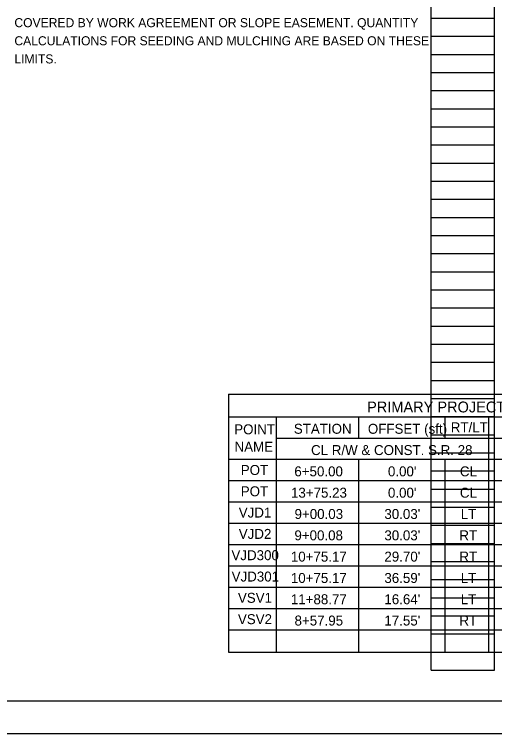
# Model space of a CAD drawing. Extents: x 0 to 34, y 0 to 22.
# Drawn here: x 17.24 to 24.66, y 0 to 11.12 of the extents above; entities that cross this region are included whole.
import ezdxf

# ---------------------------------------------------------------- set-up
doc = ezdxf.new("R2010")
doc.units = 0
for name, color, linetype in [('SH_Border', 7, 'Continuous'), ('SH_Cut_Line', 7, 'Continuous'), ('SH_Data', 7, 'Continuous'), ('SH_Text', 7, 'Continuous')]:
    doc.layers.add(name, color=color, linetype=linetype)

msp = doc.modelspace()

# ---------------------------------------------------------------- linework, layer by layer
at = {"layer": 'SH_Border'}
msp.add_lwpolyline([(1.5, 21.5), (33.5, 21.5), (33.5, 0.5), (1.5, 0.5)], close=True, dxfattribs=at)
at = {"layer": 'SH_Cut_Line'}
msp.add_lwpolyline([(0, 0), (34, 0), (34, 22), (0, 22)], close=True, dxfattribs=at)
at = {"layer": 'SH_Data'}
for p, q in [((23.68, 0.98), (23.68, 21.14)), ((24.66, 0.98), (24.66, 21.14)), ((23.68, 11.06), (24.66, 11.06)), ((23.68, 10.78), (24.66, 10.78)), ((23.68, 10.5), (24.66, 10.5)), ((23.68, 10.22), (24.66, 10.22)), ((23.68, 9.94), (24.66, 9.94)), ((23.68, 9.66), (24.66, 9.66)), ((23.68, 9.38), (24.66, 9.38)), ((23.68, 9.1), (24.66, 9.1)), ((23.68, 8.82), (24.66, 8.82)), ((23.68, 8.54), (24.66, 8.54)), ((23.68, 8.26), (24.66, 8.26)), ((23.68, 7.98), (24.66, 7.98)), ((23.68, 7.7), (24.66, 7.7)), ((23.68, 7.42), (24.66, 7.42)), ((23.68, 7.14), (24.66, 7.14)), ((23.68, 6.86), (24.66, 6.86)), ((23.68, 6.58), (24.66, 6.58)), ((23.68, 6.3), (24.66, 6.3)), ((23.68, 6.02), (24.66, 6.02)), ((23.68, 5.74), (24.66, 5.74)), ((23.68, 5.46), (24.66, 5.46)), ((20.546, 5.245), (30.939, 5.245)), ((20.546, 5.245), (20.546, 1.259)), ((23.68, 5.18), (24.66, 5.18)), ((20.546, 4.899), (30.939, 4.899)), ((21.287, 4.899), (21.287, 1.259)), ((22.555, 4.899), (22.555, 4.569)), ((23.68, 4.9), (24.66, 4.9)), ((23.889, 4.899), (23.889, 4.569)), ((24.564, 4.899), (24.564, 1.259)), ((21.287, 4.569), (27.266, 4.569)), ((23.68, 4.62), (24.66, 4.62)), ((23.68, 4.34), (24.66, 4.34)), ((20.546, 4.24), (30.939, 4.24)), ((22.555, 4.24), (22.555, 1.259)), ((23.889, 4.24), (23.889, 1.259)), ((23.68, 4.06), (24.66, 4.06)), ((20.546, 3.911), (30.939, 3.911)), ((23.68, 3.78), (24.66, 3.78)), ((20.546, 3.581), (30.939, 3.581)), ((23.68, 3.5), (24.66, 3.5)), ((20.546, 3.252), (30.939, 3.252)), ((23.68, 3.22), (24.66, 3.22)), ((20.546, 2.922), (30.939, 2.922)), ((23.68, 2.94), (24.66, 2.94)), ((20.546, 2.593), (30.939, 2.593)), ((23.68, 2.66), (24.66, 2.66)), ((23.68, 2.38), (24.66, 2.38)), ((20.546, 2.264), (30.939, 2.264)), ((23.68, 2.1), (24.66, 2.1)), ((20.546, 1.934), (30.939, 1.934)), ((23.68, 1.82), (24.66, 1.82)), ((20.546, 1.605), (30.939, 1.605)), ((23.68, 1.54), (24.66, 1.54)), ((20.546, 1.259), (30.939, 1.259)), ((23.68, 1.26), (24.66, 1.26)), ((23.68, 0.98), (24.66, 0.98))]:
    msp.add_line(p, q, dxfattribs=at)

# ---------------------------------------------------------------- texts
at = {"layer": 'SH_Text'}
for s, height, p in [('COVERED BY WORK AGREEMENT OR SLOPE EASEMENT. QUANTITY ', 0.14, (17.24, 10.92)), ('CALCULATIONS FOR SEEDING AND MULCHING ARE BASED ON THESE ', 0.14, (17.24, 10.64)), ('LIMITS.', 0.14, (17.24, 10.36)), ('PRIMARY PROJECT CONTROL AND CENTERLINE INFORMATION', 0.168, (22.69, 4.965)), ('POINT', 0.154, (20.637, 4.627)), ('STATION', 0.154, (21.558, 4.635)), ('OFFSET (sft)', 0.154, (22.702, 4.635)), ('RT/LT', 0.154, (23.983, 4.657)), ('NAME', 0.154, (20.642, 4.358)), ('CL R/W & CONST. S.R. 28', 0.154, (21.824, 4.306)), ('POT', 0.154, (20.738, 3.998)), ('6+50.00', 0.154, (21.566, 3.977)), ("0.00'", 0.154, (23.012, 3.977)), ('CL', 0.154, (24.124, 3.977)), ('POT', 0.154, (20.738, 3.669)), ('13+75.23', 0.154, (21.514, 3.647)), ("0.00'", 0.154, (23.012, 3.647)), ('CL', 0.154, (24.124, 3.647)), ('VJD1', 0.154, (20.707, 3.34)), ('9+00.03', 0.154, (21.569, 3.318)), ("30.03'", 0.154, (22.957, 3.318)), ('LT', 0.154, (24.137, 3.318)), ('VJD2', 0.154, (20.707, 3.01)), ('9+00.08', 0.154, (21.567, 2.988)), ("30.03'", 0.154, (22.957, 2.988)), ('RT', 0.154, (24.116, 2.988)), ('VJD300', 0.154, (20.594, 2.681)), ('10+75.17', 0.154, (21.512, 2.659)), ("29.70'", 0.154, (22.957, 2.659)), ('RT', 0.154, (24.116, 2.659)), ('VJD301', 0.154, (20.597, 2.351)), ('10+75.17', 0.154, (21.512, 2.329)), ("36.59'", 0.154, (22.957, 2.329)), ('LT', 0.154, (24.137, 2.329)), ('VSV1', 0.154, (20.694, 2.022)), ('11+88.77', 0.154, (21.512, 2)), ("16.64'", 0.154, (22.957, 2)), ('LT', 0.154, (24.137, 2)), ('VSV2', 0.154, (20.694, 1.692)), ('8+57.95', 0.154, (21.569, 1.671)), ("17.55'", 0.154, (22.957, 1.671)), ('RT', 0.154, (24.116, 1.671))]:
    msp.add_text(s, height=height, dxfattribs=at).set_placement(p)

doc.saveas('drawing.dxf')
